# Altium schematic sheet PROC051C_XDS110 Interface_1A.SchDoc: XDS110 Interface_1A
size 431 x 279 mm; Date: Not shown in title block; ApprovedBy: Not shown in title block; CheckedBy: Not shown in title block; Author: Not shown in title block; CompanyName: Not shown in title block; Engineer: Not shown in title block; Organization: Not shown in title block; Address1: Not shown in title block; Address2: Not shown in title block; Address3: Not shown in title block; Address4: Not shown in title block; DocumentNumber: 12; Revision: Use project parameter SCH_Rev; SheetNumber: 12; SheetTotal: 16; PageSetup: Record=PageOptions¦CenterHorizontal=True¦CenterVertical=True¦PrintScale=1.00¦XCorrection=1.00¦YCorrection=1.00¦PrintKind=0¦BorderSize=5000000¦LeftOffset=0¦BottomOffset=0¦Orientation=2¦PaperLength=1000¦PaperWidth=1000¦Scale=100¦PaperSource=15¦PrintQuality=600¦MediaType=1¦DitherType=10¦PaperKind=Letter¦PrintScaleMode=1
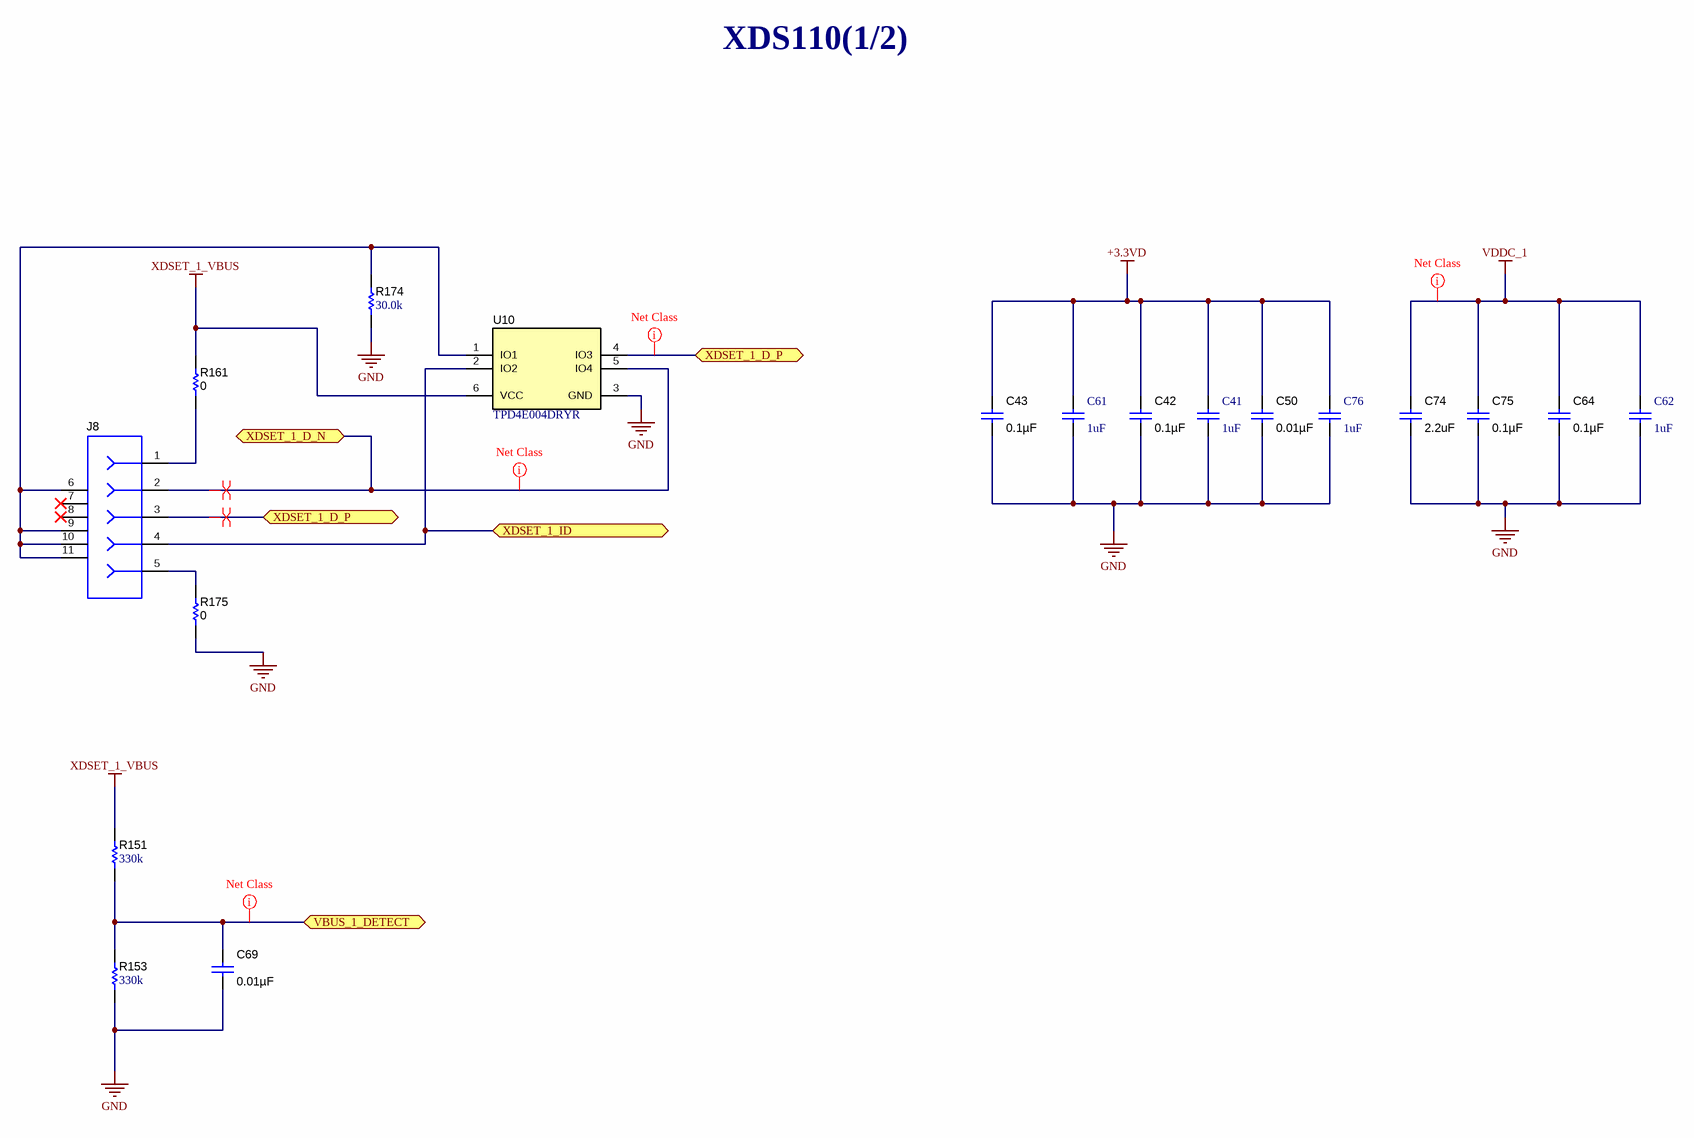
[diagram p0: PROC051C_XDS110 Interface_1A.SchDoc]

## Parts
C41  ValueDisplayed: 1uF  [0402_070]  (hidden comment: GCM155C71A105KE38D)
C42  ValueDisplayed: 0.1µF  [0402L]  (hidden comment: C0402C104K8RACTU)
C43  ValueDisplayed: 0.1µF  [0402L]  (hidden comment: C0402C104K8RACTU)
C50  ValueDisplayed: 0.01µF  [0402L]  (hidden comment: C0402C103K4RACTU)
C61  ValueDisplayed: 1uF  [0402_070]  (hidden comment: GCM155C71A105KE38D)
C62  ValueDisplayed: 1uF  [0402_070]  (hidden comment: GCM155C71A105KE38D)
C64  ValueDisplayed: 0.1µF  [0402L]  (hidden comment: C0402C104K8RACTU)
C69  ValueDisplayed: 0.01µF  [0402L]  (hidden comment: C0402C103K4RACTU)
C74  ValueDisplayed: 2.2uF  [0402_065L]  (hidden comment: C1005X7S1A225K050BC)
C75  ValueDisplayed: 0.1µF  [0402L]  (hidden comment: C0402C104K8RACTU)
C76  ValueDisplayed: 1uF  [0402_070]  (hidden comment: GCM155C71A105KE38D)
J8  105017-0001  [CONN_105017-0001]  (value not drawn)
R151  ValueDisplayed: 330k  [0402L]  (hidden comment: CRCW0402330KFKED)
R153  ValueDisplayed: 330k  [0402L]  (hidden comment: CRCW0402330KFKED)
R161  ValueDisplayed: 0  [0603]  (hidden comment: MCT06030Z0000ZP500)
R174  ValueDisplayed: 30.0k  [0402L]  (hidden comment: CRCW040230K0FKED)
R175  ValueDisplayed: 0  [0603]  (hidden comment: MCT06030Z0000ZP500)
U10  TPD4E004DRYR  [DRY0006A]

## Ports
VBUS_1_DETECT, XDSET_1_D_N, XDSET_1_D_P, XDSET_1_ID

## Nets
+3.3VD: C41.1 C42.2 C43.2 C50.2 C61.1 C76.1
GND: C41.2 C42.1 C43.1 C50.1 C61.2 C62.2 C64.1 C69.1 C74.1 C75.1 C76.2 R153.1 R174.1 R175.1 U10.3(GND)
VDDC_1: C62.1 C64.2 C74.2 C75.2
XDSET_1_VBUS: R151.2 R161.2 U10.6(VCC)
VBUS_1_DETECT: C69.2 R151.1 R153.2 ; port VBUS_1_DETECT
XDSET_1_D_N: J8.2 U10.5(IO4) ; port XDSET_1_D_N
XDSET_1_D_P: J8.3 U10.4(IO3) ; port XDSET_1_D_P
XDSET_1_ID: J8.4 U10.2(IO2) ; port XDSET_1_ID
NetJ8_1: J8.1 R161.1
NetJ8_5: J8.5 R175.2
NetJ8_6: J8.6 J8.9 J8.10 J8.11 R174.2 U10.1(IO1)

Not connected (* = marked no-connect by the designer): J8 7* 8*

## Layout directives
net class PWR: VBUS_1_DETECT, VDDC_1
net class USB: XDSET_1_D_N, XDSET_1_D_P
differential pair: XDSET_1_D_N, XDSET_1_D_P

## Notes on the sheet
- XDS110(1/2)

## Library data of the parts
C41 C61 C62 C76 = CMP-0006349-2: CAP, CERM, 1 uF, 10 V, +/- 10%, X7S, AEC-Q200 Grade 1, 0402; Manufacturer: MuRata; TaMin_C: -55°C; Polarized: N; SizeAreaWB_mm2: 3; Value1: Unknown; U/M: EA; Value: 1uF; TaMax_C: 125°C; SizeZ_mm: 0.7; SizeX_mm: 1; SizeY_mm: 0.5; Cap_Case: 0402; Value2: 10V; CompType: Capacitor; AEC Qualified: Y; Cap_F: 1µF; AEC Category: Q200
C42 C43 C64 C75 = CMP-0078241-1: CAP, CERM, 0.1 µF, 10 V,+/- 10%, X7R, 0402; Manufacturer: Kemet; TaMin_C: -55°C; Polarized: N; SizeAreaWB_mm2: 3; U/M: EA; Value: 0.1uF; TaMax_C: 125°C; SizeZ_mm: 0.6; SizeX_mm: 1; SizeY_mm: 0.5; Cap_Case: 0402; Value2: 10V; Cap_F: 100nF; AEC Category: Q200
C50 C69 = CMP-0078218-1: CAP, CERM, 0.01 µF, 16 V,+/- 10%, X7R, 0402; Manufacturer: Kemet; TaMin_C: -55°C; Polarized: N; Green_Lifecycle: Active; SizeAreaWB_mm2: 3; Green_REACh: Passed; U/M: EA; Value: 0.01uF; TaMax_C: 125°C; SizeZ_mm: 0.6; SizeX_mm: 1; SizeY_mm: 0.5; Cap_Case: 0402; Value2: 16V; Cap_F: 10nF; AEC Category: Q200
C74 = CMP-0006302-2: CAP, CERM, 2.2 uF, 10 V, +/- 10%, X7S, 0402; Manufacturer: TDK; TaMin_C: -55°C; ESR_ohm: 5.925m; Polarized: N; SizeAreaWB_mm2: 3; Value1: 0.005925 ohm; U/M: EA; Value: 2.2uF; TaMax_C: 125°C; SizeZ_mm: 0.65; SizeX_mm: 1; SizeY_mm: 0.5; Cap_Case: 0402_065; Value2: 10V; CompType: Capacitor; Cap_F: 2.2µF; IRMS_A: 2.05591A; AEC Category: Q200
J8 = CMP-0055293-1: Connector, Receptacle, Micro-USB Type B, R/A, Bottom Mount SMT; Manufacturer: Molex; CNHeader: FALSE; Green_Lifecycle: Active; Gender: Female; Green_REACh: Passed; CompType: USB; CT: TRUE
R151 R153 = CMP-0078210-2: RES, 330 k, 1%, 0.063 W, AEC-Q200 Grade 0, 0402; Manufacturer: Vishay-Dale; SizeArea_mm2: 0.5; AEC Qualified: Y; AEC Category: Q200; Value: 330k; SizeZ_mm: 0.6; TempCo: 100 ppm/C; AEC Grade: 0; Power_W: 63mW; VDC_V: 50V; Value2: 0.063W; SizeX_mm: 1
R161 R175 = CMP-0025884-3: RES, 0, 5%, 0.125 W, 0603; Manufacturer: Vishay/Beyschlag; Power_W: 125mW; TempCo: ppm/C; Value_Code: 0000; U/M: EA; Value: 0; EIA_Code: E24; SizeX_mm: 1.6; SizeY_mm: 0.8; SizeZ_mm: 1; Value2: 0.125W; SizeArea_mm2: 1.28; AEC Qualified: N; AEC Category: Q200
R174 = CMP-0078244-2: RES, 30.0 k, 1%, 0.063 W, AEC-Q200 Grade 0, 0402; Manufacturer: Vishay-Dale; Power_W: 63mW; Green_Lifecycle: Active; TempCo: 100 ppm/C; Value_Code: 30k0; Green_REACh: Passed; Value: 30.0k; Res_ohm: 30k; SizeX_mm: 1; SizeY_mm: 0.5; SizeZ_mm: 0.6; Value2: 0.063W; AEC Qualified: Y; VDC_V: 50V; AEC Grade: 0; AEC Category: Q200
U10 = CMP-0043115-3: 4-Channel ESD Protection Array for High-Speed Data Interfaces, DRY0006A (USON-6); Manufacturer: Texas Instruments; IO Leakage Current(nA): 1; USB High Speed: TRUE; IO Capacitance(Typ)(pF): 1.6; Eco-Plan: Green (RoHS & no Sb/Br); IEC 61000-4-2 Contact(+/- kV): 8; Breakdown Voltage(Min)(V): 6; IEC 61000-4-2 Air-Gap(+/- kV): 12; AEC Category: Q200; AEC Qualified: N; CompType: IC; SizeArea_mm2: 1.45; SizeAreaWB_mm2: 4.9; SizeX_mm: 1.0; SizeZ_mm: 0.6; Rating: Catalog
